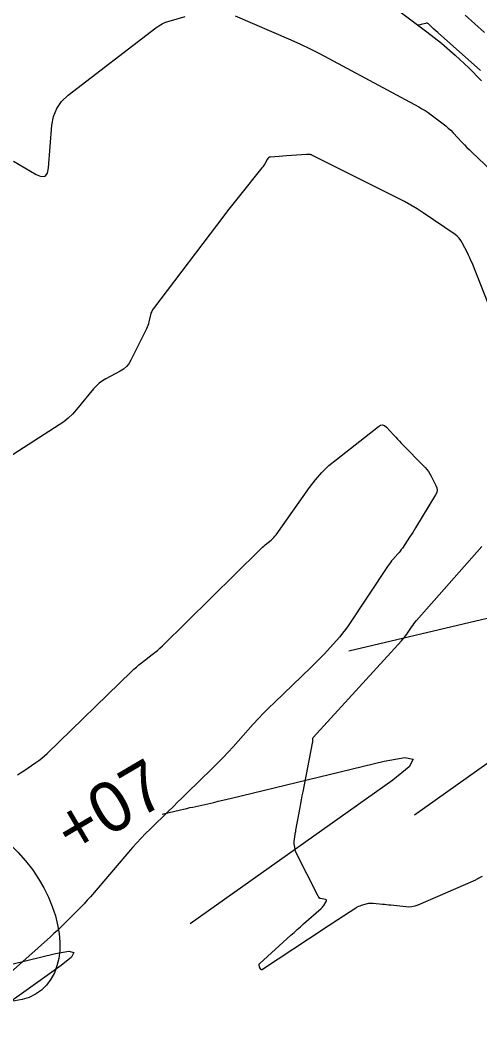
# Model space of a CAD drawing. Extents: x 1005228 to 1008882, y 1883389 to 1885754.
# Drawn here: x 1008093.9 to 1008151.3, y 1884226.5 to 1884352.9 of the extents above; entities that cross this region are included whole.
import ezdxf

# ---------------------------------------------------------------- set-up
doc = ezdxf.new("R2010")
doc.units = 0
for name, color, linetype in [('ATDIMS', 7, 'Continuous'), ('C-ANNO-NOTE', 7, 'Continuous'), ('R_Erosion', 7, 'Continuous'), ('S_BASELINE', 7, 'Continuous'), ('S_BRIDGE', 7, 'Continuous'), ('TSOBSTACLE', 7, 'Continuous')]:
    doc.layers.add(name, color=color, linetype=linetype)

msp = doc.modelspace()

# ---------------------------------------------------------------- linework, layer by layer
at = {"layer": 'ATDIMS'}
msp.add_lwpolyline([(1008111.63, 1884253.77), (1008113.94, 1884254.33), (1008114.33, 1884254.42), (1008114.71, 1884254.51), (1008115.1, 1884254.6), (1008115.49, 1884254.68), (1008118.08, 1884255.26), (1008118.64, 1884255.39), (1008119.2, 1884255.52), (1008119.76, 1884255.65), (1008120.32, 1884255.79), (1008139.37, 1884260.4), (1008141.95, 1884260.87), (1008143, 1884260.63), (1008142.49, 1884259.68), (1008140.44, 1884258.03), (1008115.16, 1884240.11)], dxfattribs=at)
at = {"layer": 'C-ANNO-NOTE'}
for points in [[(1008135.15, 1884358.61), (1008144.7, 1884351.4), (1008146.5, 1884349.98), (1008148.24, 1884348.48), (1008149.92, 1884346.92), (1008151.53, 1884345.28)], [(1008093.1, 1884335.28), (1008095.93, 1884333.62), (1008096.55, 1884333.36), (1008097.02, 1884333.41), (1008097.32, 1884333.76), (1008097.47, 1884334.42), (1008097.88, 1884339.75), (1008098.07, 1884340.86), (1008098.48, 1884341.85), (1008099.09, 1884342.73), (1008099.91, 1884343.5), (1008110.84, 1884351.9), (1008111.23, 1884352.18), (1008111.65, 1884352.41), (1008112.08, 1884352.6), (1008112.53, 1884352.75), (1008114.5, 1884353.31)], [(1008120.74, 1884353.42), (1008127.71, 1884350.4), (1008128.92, 1884349.86), (1008130.11, 1884349.29), (1008131.3, 1884348.7), (1008132.47, 1884348.09), (1008143.69, 1884342.05), (1008144.08, 1884341.82), (1008144.47, 1884341.59), (1008144.85, 1884341.33), (1008145.21, 1884341.07), (1008146.72, 1884339.93), (1008147.04, 1884339.67), (1008147.36, 1884339.4), (1008147.67, 1884339.12), (1008147.96, 1884338.82), (1008149.11, 1884337.59), (1008149.4, 1884337.29), (1008149.7, 1884336.99), (1008150, 1884336.69), (1008150.3, 1884336.4), (1008157.61, 1884329.43)], [(1008152.43, 1884317.31), (1008150.33, 1884322.57), (1008150.2, 1884322.89), (1008150.06, 1884323.21), (1008149.91, 1884323.53), (1008149.75, 1884323.84), (1008149.12, 1884325.09), (1008148.94, 1884325.39), (1008148.73, 1884325.66), (1008148.49, 1884325.9), (1008148.22, 1884326.11), (1008144.24, 1884328.82), (1008143.47, 1884329.32), (1008142.69, 1884329.8), (1008141.89, 1884330.25), (1008141.07, 1884330.67), (1008130.32, 1884336.04), (1008130.27, 1884336.06), (1008130.22, 1884336.08), (1008130.16, 1884336.09), (1008130.11, 1884336.09), (1008129.88, 1884336.1), (1008129.82, 1884336.1), (1008129.76, 1884336.1), (1008129.71, 1884336.1), (1008129.65, 1884336.1), (1008127.17, 1884335.92), (1008126.72, 1884335.89), (1008126.26, 1884335.86), (1008125.19, 1884335.79), (1008125.04, 1884335.76), (1008124.92, 1884335.7), (1008124.82, 1884335.61), (1008124.74, 1884335.49), (1008124.45, 1884334.95), (1008124.37, 1884334.82), (1008124.29, 1884334.69), (1008124.21, 1884334.57), (1008124.11, 1884334.45), (1008121.3, 1884330.95), (1008120.8, 1884330.33), (1008120.3, 1884329.7), (1008119.81, 1884329.07), (1008119.33, 1884328.44), (1008110.57, 1884316.89), (1008110.44, 1884316.7), (1008110.34, 1884316.51), (1008110.25, 1884316.3), (1008110.19, 1884316.09), (1008109.98, 1884315.21), (1008109.92, 1884314.99), (1008109.85, 1884314.78), (1008109.77, 1884314.57), (1008109.67, 1884314.36), (1008107.73, 1884310.43), (1008107.48, 1884310), (1008107.18, 1884309.63), (1008106.82, 1884309.32), (1008106.4, 1884309.06), (1008104.62, 1884308.12), (1008104.19, 1884307.87), (1008103.8, 1884307.58), (1008103.43, 1884307.25), (1008103.09, 1884306.88), (1008100.94, 1884304.27), (1008100.45, 1884303.72), (1008099.93, 1884303.22), (1008099.37, 1884302.76), (1008098.77, 1884302.35), (1008090.42, 1884297.01)], [(1008151.59, 1884246.02), (1008151.18, 1884245.78), (1008151.07, 1884245.73), (1008150.97, 1884245.67), (1008150.86, 1884245.62), (1008150.75, 1884245.57), (1008143.57, 1884242.44), (1008143.2, 1884242.31), (1008142.82, 1884242.23), (1008142.44, 1884242.19), (1008142.05, 1884242.21), (1008140.19, 1884242.42), (1008139.93, 1884242.45), (1008139.67, 1884242.48), (1008139.41, 1884242.5), (1008139.15, 1884242.53), (1008137.97, 1884242.64), (1008137.78, 1884242.65), (1008137.59, 1884242.64), (1008137.41, 1884242.62), (1008137.22, 1884242.58), (1008136.49, 1884242.38), (1008136.31, 1884242.32), (1008136.14, 1884242.25), (1008135.97, 1884242.17), (1008135.81, 1884242.07), (1008133.57, 1884240.6), (1008133.14, 1884240.32), (1008132.71, 1884240.03), (1008132.29, 1884239.75), (1008131.86, 1884239.47), (1008124.17, 1884234.39), (1008124.12, 1884234.36), (1008124.08, 1884234.36), (1008124.04, 1884234.38), (1008124.01, 1884234.41), (1008123.86, 1884234.6), (1008123.83, 1884234.65), (1008123.81, 1884234.69), (1008123.79, 1884234.74), (1008123.78, 1884234.79), (1008123.76, 1884234.99), (1008123.75, 1884235.04), (1008123.76, 1884235.09), (1008123.79, 1884235.13), (1008123.82, 1884235.17), (1008127.72, 1884238.68), (1008128.11, 1884239.04), (1008128.5, 1884239.39), (1008128.9, 1884239.74), (1008129.3, 1884240.09), (1008131.48, 1884242.01), (1008131.58, 1884242.1), (1008131.67, 1884242.2), (1008131.75, 1884242.3), (1008131.83, 1884242.41), (1008132.14, 1884242.88), (1008132.18, 1884242.97), (1008132.18, 1884243.04), (1008132.13, 1884243.09), (1008132.04, 1884243.13), (1008131.4, 1884243.25), (1008131.36, 1884243.26), (1008131.34, 1884243.27), (1008131.31, 1884243.29), (1008131.29, 1884243.32), (1008131.21, 1884243.42), (1008131.19, 1884243.45), (1008131.18, 1884243.48), (1008131.16, 1884243.51), (1008131.14, 1884243.54), (1008128.39, 1884248.96), (1008128.34, 1884249.07), (1008128.3, 1884249.18), (1008128.26, 1884249.29), (1008128.24, 1884249.41), (1008128.15, 1884249.89), (1008128.13, 1884250.01), (1008128.12, 1884250.13), (1008128.13, 1884250.25), (1008128.14, 1884250.37), (1008128.31, 1884251.54), (1008128.32, 1884251.56), (1008128.32, 1884251.58), (1008128.32, 1884251.6), (1008128.33, 1884251.62), (1008128.34, 1884251.7), (1008128.35, 1884251.74), (1008128.35, 1884251.77), (1008128.87, 1884254.63), (1008128.96, 1884255.11), (1008129.05, 1884255.59), (1008129.14, 1884256.08), (1008129.23, 1884256.56), (1008130.42, 1884262.66), (1008130.43, 1884262.72), (1008130.44, 1884262.78), (1008130.44, 1884262.84), (1008130.44, 1884262.9), (1008130.44, 1884263.14), (1008130.44, 1884263.19), (1008130.45, 1884263.25), (1008130.48, 1884263.3), (1008130.51, 1884263.35), (1008141.53, 1884275.41), (1008141.71, 1884275.61), (1008141.87, 1884275.81), (1008142.03, 1884276.02), (1008142.18, 1884276.24), (1008142.77, 1884277.11), (1008142.92, 1884277.33), (1008143.07, 1884277.54), (1008143.24, 1884277.75), (1008143.41, 1884277.95), (1008151.56, 1884287.18)]]:
    msp.add_lwpolyline(points, dxfattribs=at)
at = {"layer": 'R_Erosion'}
msp.add_ellipse((1008087.84, 1884242.39), major_axis=(8.74, -10.55), ratio=0.638788, dxfattribs=at)
at = {"layer": 'S_BRIDGE'}
msp.add_lwpolyline([(1008093.6, 1884258.69), (1008093.98, 1884258.95), (1008094.36, 1884259.21), (1008095.88, 1884260.22), (1008096.26, 1884260.48), (1008096.62, 1884260.76), (1008096.97, 1884261.06), (1008097.3, 1884261.37), (1008107.81, 1884271.58), (1008108.12, 1884271.87), (1008108.43, 1884272.15), (1008108.75, 1884272.42), (1008109.08, 1884272.68), (1008110.41, 1884273.7), (1008110.73, 1884273.96), (1008111.05, 1884274.22), (1008111.36, 1884274.5), (1008111.67, 1884274.79), (1008123.83, 1884286.77), (1008124, 1884286.93), (1008124.17, 1884287.09), (1008124.34, 1884287.24), (1008124.52, 1884287.39), (1008125.24, 1884287.98), (1008125.42, 1884288.13), (1008125.58, 1884288.3), (1008125.73, 1884288.47), (1008125.87, 1884288.66), (1008130.05, 1884294.55), (1008130.79, 1884295.52), (1008131.59, 1884296.43), (1008132.46, 1884297.28), (1008133.4, 1884298.06), (1008138.66, 1884302.17), (1008138.92, 1884302.33), (1008139.17, 1884302.36), (1008139.42, 1884302.28), (1008139.65, 1884302.09), (1008140.57, 1884301.07), (1008140.8, 1884300.82), (1008141.03, 1884300.57), (1008141.26, 1884300.32), (1008141.5, 1884300.07), (1008144.46, 1884297.05), (1008144.68, 1884296.8), (1008144.88, 1884296.54), (1008145.06, 1884296.27), (1008145.22, 1884295.98), (1008145.83, 1884294.8), (1008145.94, 1884294.51), (1008145.97, 1884294.22), (1008145.92, 1884293.93), (1008145.79, 1884293.64), (1008143.29, 1884289.52), (1008143.11, 1884289.22), (1008142.92, 1884288.93), (1008142.73, 1884288.64), (1008142.54, 1884288.35), (1008141.64, 1884287), (1008141.5, 1884286.81), (1008141.36, 1884286.62), (1008141.22, 1884286.44), (1008141.07, 1884286.26), (1008140.44, 1884285.56), (1008140.29, 1884285.38), (1008140.14, 1884285.2), (1008140.01, 1884285.01), (1008139.87, 1884284.82), (1008134.87, 1884277.3), (1008134.53, 1884276.83), (1008134.18, 1884276.36), (1008133.82, 1884275.91), (1008133.43, 1884275.47), (1008131.86, 1884273.75), (1008131.46, 1884273.32), (1008131.05, 1884272.9), (1008130.64, 1884272.49), (1008130.22, 1884272.08), (1008125.65, 1884267.72), (1008124.97, 1884267.06), (1008124.31, 1884266.39), (1008123.66, 1884265.71), (1008123.02, 1884265.01), (1008120.5, 1884262.21), (1008119.87, 1884261.51), (1008119.22, 1884260.82), (1008118.56, 1884260.15), (1008117.89, 1884259.48), (1008114.72, 1884256.39), (1008114.15, 1884255.83), (1008113.58, 1884255.28), (1008113, 1884254.72), (1008112.43, 1884254.16), (1008110.15, 1884251.93), (1008109.58, 1884251.37), (1008109.03, 1884250.79), (1008108.49, 1884250.21), (1008107.96, 1884249.61), (1008102.68, 1884243.49), (1008102.29, 1884243.05), (1008101.9, 1884242.61), (1008101.49, 1884242.19), (1008101.08, 1884241.77), (1008099.41, 1884240.1), (1008098.99, 1884239.68), (1008098.56, 1884239.28), (1008098.13, 1884238.88), (1008097.69, 1884238.48), (1008087.68, 1884229.57)], dxfattribs=at)
at = {"layer": 'TSOBSTACLE'}
for points in [[(1008151.9, 1884351.32), (1008149.46, 1884353.5)], [(1008151.39, 1884346.58), (1008146.1, 1884351.29), (1008146.06, 1884351.32), (1008145.57, 1884351.76), (1008145.55, 1884351.77), (1008145.54, 1884351.79), (1008145.52, 1884351.8), (1008145.5, 1884351.82), (1008144.89, 1884352.39), (1008144.8, 1884352.45), (1008144.72, 1884352.48), (1008144.62, 1884352.49), (1008144.52, 1884352.47), (1008143.97, 1884352.32), (1008143.87, 1884352.29), (1008143.61, 1884352.23)], [(1008143.13, 1884253.72), (1008187.19, 1884284.95)], [(1008152.22, 1884278.22), (1008134.96, 1884274.12)], [(1008085.68, 1884233.31), (1008098.35, 1884236.39), (1008099.98, 1884236.68), (1008100.63, 1884236.53), (1008100.32, 1884235.93), (1008099.03, 1884234.9), (1008087.2, 1884226.51)]]:
    msp.add_lwpolyline(points, dxfattribs=at)

# ---------------------------------------------------------------- texts
at = {"layer": 'S_BASELINE'}
msp.add_text('+07', height=6.25, rotation=30.4129, dxfattribs=at).set_placement((1008100.56, 1884248.39))

doc.saveas('drawing.dxf')
